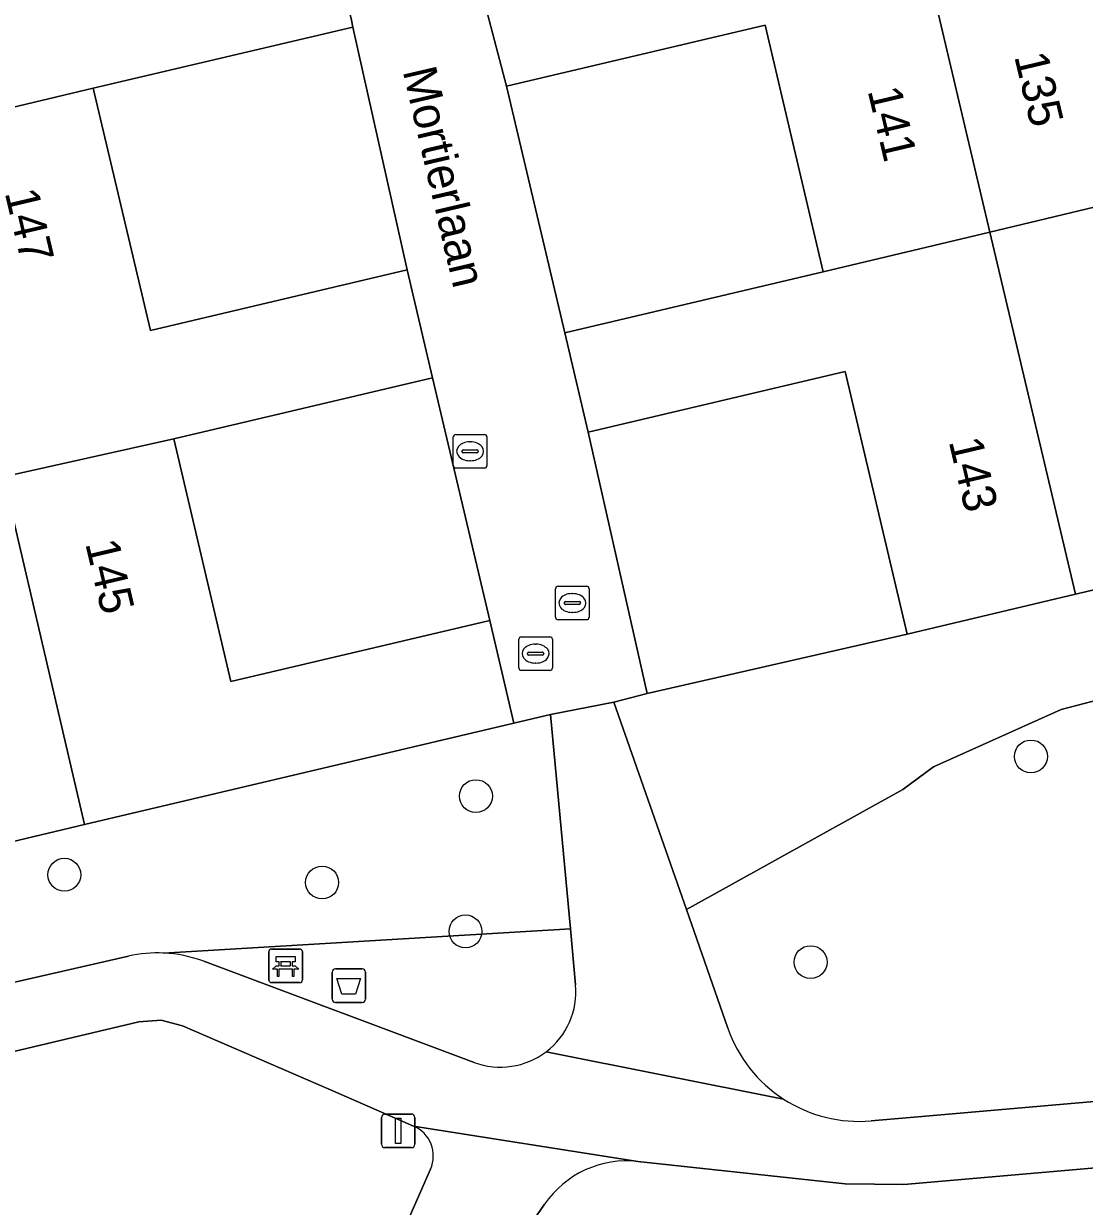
# Model space of a CAD drawing. Extents: x 162989 to 165008, y 383432 to 384338.
# Drawn here: x 164115.4 to 164146.97, y 383964.71 to 383999.9 of the extents above; entities that cross this region are included whole.
import ezdxf

# ---------------------------------------------------------------- set-up
doc = ezdxf.new("R2010")
doc.units = 0
for name, color, linetype in [('IMGEO_Afvalbak', 7, 'Continuous'), ('IMGEO_Bank', 7, 'Continuous'), ('IMGEO_Boom', 7, 'Continuous'), ('IMGEO_Brandkraan', 7, 'Continuous'), ('IMGEO_Erf', 7, 'Continuous'), ('IMGEO_Groenvoorziening', 7, 'Continuous'), ('IMGEO_Kolk', 7, 'Continuous'), ('IMGEO_Lichtmast', 7, 'Continuous'), ('IMGEO_Openbare_ruimte_label', 7, 'Continuous'), ('IMGEO_Pand', 7, 'Continuous'), ('IMGEO_Pand_nummerreeks', 7, 'Continuous'), ('IMGEO_Rioolput', 7, 'Continuous'), ('IMGEO_Voetpad_halfverhard', 7, 'Continuous'), ('IMGEO_Voetpad_open', 7, 'Continuous')]:
    doc.layers.add(name, color=color, linetype=linetype)

msp = doc.modelspace()

# ---------------------------------------------------------------- linework, layer by layer
at = {"layer": 'IMGEO_Afvalbak'}
for p, q in [((164124.581, 383970.875), (164124.581, 383971.675)), ((164124.581, 383971.675), (164124.581, 383970.875)), ((164124.681, 383971.775), (164125.471, 383971.775)), ((164125.471, 383971.775), (164124.681, 383971.775)), ((164125.571, 383971.675), (164125.571, 383970.875)), ((164125.571, 383970.875), (164125.571, 383971.675)), ((164125.471, 383970.775), (164124.681, 383970.775)), ((164124.681, 383970.775), (164125.471, 383970.775))]:
    msp.add_line(p, q, dxfattribs=at)
msp.add_lwpolyline([(164124.724, 383971.489), (164125.428, 383971.489), (164125.279, 383971.019), (164124.873, 383971.019), (164124.724, 383971.489)], dxfattribs=at)
for centre, start, end in [((164124.681, 383971.675), 90, 180), ((164124.681, 383971.675), 90, 180), ((164125.471, 383971.675), 0, 90), ((164125.471, 383971.675), 360, 90), ((164124.681, 383970.875), 180, 270), ((164124.681, 383970.875), 180, 270), ((164125.471, 383970.875), 270, 0), ((164125.471, 383970.875), 270, 0)]:
    msp.add_arc(centre, 0.1, start, end, dxfattribs=at)
at = {"layer": 'IMGEO_Bank'}
for p, q in [((164122.696, 383971.439), (164122.696, 383972.28)), ((164122.696, 383972.28), (164122.696, 383971.439)), ((164122.771, 383972.364), (164123.612, 383972.364)), ((164123.612, 383972.364), (164122.771, 383972.364)), ((164123.696, 383972.289), (164123.696, 383971.448)), ((164123.696, 383971.448), (164123.696, 383972.289)), ((164123.005, 383971.87), (164123.005, 383971.976)), ((164123.049, 383971.976), (164123.049, 383971.87)), ((164123.337, 383971.982), (164123.055, 383971.982)), ((164123.055, 383971.864), (164123.337, 383971.864)), ((164123.343, 383971.87), (164123.343, 383971.976)), ((164123.387, 383971.976), (164123.387, 383971.87)), ((164123.393, 383971.762), (164123, 383971.762)), ((164123.621, 383971.364), (164122.78, 383971.364)), ((164122.78, 383971.364), (164123.621, 383971.364))]:
    msp.add_line(p, q, dxfattribs=at)
for points in [[(164122.943, 383971.762), (164122.801, 383971.762), (164122.913, 383971.864), (164122.999, 383971.864)], [(164122.999, 383971.982), (164122.913, 383971.982), (164122.913, 383972.143), (164123.476, 383972.143), (164123.476, 383971.982), (164123.393, 383971.982)], [(164123.393, 383971.864), (164123.476, 383971.864), (164123.588, 383971.762), (164123.449, 383971.762)], [(164122.993, 383971.755), (164122.993, 383971.548), (164122.95, 383971.548), (164122.95, 383971.755)], [(164123.443, 383971.755), (164123.443, 383971.548), (164123.399, 383971.548), (164123.399, 383971.755)]]:
    msp.add_lwpolyline(points, dxfattribs=at)
for centre, radius, start, end in [((164122.774, 383972.286), 0.0779, 92.4484, 184.2845), ((164122.774, 383972.286), 0.0779, 92.4484, 184.2845), ((164123.618, 383972.286), 0.0779, 2.4484, 94.2845), ((164123.618, 383972.286), 0.0779, 2.4484, 94.2845), ((164122.998, 383971.975), 0.00671, 2.8957, 87.1043), ((164122.998, 383971.871), 0.00671, 272.8957, 357.1043), ((164123.055, 383971.975), 0.00671, 92.8957, 177.1043), ((164123.055, 383971.871), 0.00671, 182.8957, 267.1043), ((164123.337, 383971.975), 0.00671, 2.8957, 87.1043), ((164123.337, 383971.871), 0.00671, 272.8957, 357.1043), ((164123.394, 383971.975), 0.00671, 92.8957, 177.1043), ((164123.394, 383971.871), 0.00671, 182.8957, 267.1043), ((164122.943, 383971.755), 0.00671, 2.8957, 87.1043), ((164123, 383971.755), 0.00671, 92.8957, 177.1043), ((164123.392, 383971.755), 0.00671, 2.8957, 87.1043), ((164123.449, 383971.755), 0.00671, 92.8957, 177.1043), ((164123.618, 383971.442), 0.0779, 272.4484, 4.2845), ((164123.618, 383971.442), 0.0779, 272.4484, 4.2845), ((164122.774, 383971.442), 0.0779, 182.4484, 274.2845), ((164122.774, 383971.442), 0.0779, 182.4484, 274.2845)]:
    msp.add_arc(centre, radius, start, end, dxfattribs=at)
at = {"layer": 'IMGEO_Boom'}
for centre in [(164145.379, 383978.094), (164128.86, 383976.914), (164116.611, 383974.574), (164124.281, 383974.344), (164128.549, 383972.889), (164138.821, 383971.974)]:
    msp.add_circle(centre, 0.489, dxfattribs=at)
at = {"layer": 'IMGEO_Brandkraan'}
for p, q in [((164131.23, 383982.235), (164131.23, 383983.087)), ((164131.305, 383983.161), (164132.157, 383983.161)), ((164132.231, 383983.087), (164132.231, 383982.235)), ((164131.718, 383982.941), (164131.743, 383982.941)), ((164131.489, 383982.655), (164131.489, 383982.667)), ((164131.927, 383982.618), (164131.529, 383982.618)), ((164131.532, 383982.704), (164131.93, 383982.704)), ((164131.741, 383982.381), (164131.716, 383982.381)), ((164131.973, 383982.667), (164131.973, 383982.655)), ((164132.157, 383982.161), (164131.305, 383982.161))]:
    msp.add_line(p, q, dxfattribs=at)
for points in [[(164131.23, 383982.235), (164131.23, 383983.087)], [(164131.305, 383983.161), (164132.157, 383983.161)], [(164132.231, 383983.087), (164132.231, 383982.235)], [(164132.157, 383982.161), (164131.305, 383982.161)]]:
    msp.add_lwpolyline(points, dxfattribs=at)
for centre, radius, start, end in [((164131.307, 383983.085), 0.0765, 91.552, 178.448), ((164131.307, 383983.085), 0.0765, 91.552, 178.448), ((164132.155, 383983.085), 0.0765, 1.552, 88.448), ((164132.155, 383983.085), 0.0765, 1.552, 88.448), ((164131.529, 383982.664), 0.0403, 85.8775, 175.7526), ((164131.526, 383982.654), 0.0366, 178.938, 274.7102), ((164131.93, 383982.661), 0.043, 264.8664, 352.4533), ((164131.934, 383982.666), 0.0386, 1.7309, 96.639), ((164131.307, 383982.237), 0.0765, 181.552, 268.448), ((164131.307, 383982.237), 0.0765, 181.552, 268.448), ((164132.155, 383982.237), 0.0765, 271.552, 358.448), ((164132.155, 383982.237), 0.0765, 271.552, 358.448)]:
    msp.add_arc(centre, radius, start, end, dxfattribs=at)
for centre, major_axis, ratio, start_param, end_param in [((164131.717, 383982.661), (-0.387, 0.002), 0.722429, 4.712389, 7.853982), ((164131.742, 383982.661), (-0.39, 0.002), 0.717154, 1.570796, 4.712389)]:
    msp.add_ellipse(centre, major_axis=major_axis, ratio=ratio, start_param=start_param, end_param=end_param, dxfattribs=at)
at = {"layer": 'IMGEO_Erf'}
for points in [[(164125.199, 383999.801), (164117.47, 383997.977), (164119.171, 383990.768), (164126.813, 383992.571)], [(164131.502, 383990.704), (164139.198, 383992.52), (164137.466, 383999.857), (164129.77, 383998.041)], [(164141.692, 383981.736), (164139.849, 383989.547), (164132.201, 383987.742), (164133.953, 383979.965)], [(164127.57, 383989.362), (164119.865, 383987.544), (164121.568, 383980.327), (164129.269, 383982.144)]]:
    msp.add_lwpolyline(points, close=True, dxfattribs=at)
at = {"layer": 'IMGEO_Groenvoorziening'}
msp.add_lwpolyline([(164159.574, 383985.925), (164159.409, 383985.929), (164157.397, 383985.441), (164151.729, 383984.104), (164146.71, 383982.92), (164141.692, 383981.736), (164133.953, 383979.965), (164132.966, 383979.708), (164135.124, 383973.54), (164141.563, 383977.111), (164142.476, 383977.785), (164146.283, 383979.493), (164149.698, 383980.387), (164152.237, 383980.784), (164155.081, 383980.775), (164157.567, 383980.052), (164160.789, 383982.372), (164160.857, 383982.761), (164160.504, 383986.121)], close=True, dxfattribs=at)
for points in [[(164157.317, 383979.515), (164157.567, 383980.052), (164155.081, 383980.775), (164152.237, 383980.784), (164149.698, 383980.387), (164146.283, 383979.493), (164142.476, 383977.785), (164141.563, 383977.111), (164135.124, 383973.54), (164136.36, 383970.005)], [(164119.565, 383972.245), (164131.671, 383972.965), (164131.077, 383979.343), (164129.992, 383979.081), (164117.21, 383976.065), (164112.873, 383975.042), (164113.781, 383971.067), (164118.524, 383972.15)], [(164131.671, 383972.965), (164119.565, 383972.245)], [(164131.826, 383971.297), (164131.671, 383972.965)], [(164120.758, 383972.001), (164128.805, 383968.991)], [(164127.006, 383967.096), (164124.527, 383968.171), (164120.127, 383970.08), (164119.488, 383970.242), (164118.83, 383970.195), (164103.103, 383966.472), (164101.5, 383965.727), (164095.46, 383961.254), (164094.962, 383960.741), (164094.409, 383959.248), (164098.81, 383957.196), (164100.331, 383956.769), (164101.117, 383956.676), (164102.633, 383956.731), (164107.853, 383957.563), (164114.758, 383957.879), (164124.472, 383958.604), (164124.472, 383958.607), (164124.732, 383959.495), (164127.509, 383965.814)], [(164140.621, 383967.251), (164141.789, 383967.352), (164152.516, 383968.282)], [(164154.954, 383966.519), (164141.592, 383965.354), (164139.852, 383965.372), (164133.68, 383966.044)], [(164130.902, 383964.768), (164126.835, 383958.84), (164126.613, 383958.341), (164126.806, 383955.345), (164128.25, 383955.458), (164141.508, 383956.62), (164140.962, 383962.858), (164154.924, 383964.08), (164155.686, 383964.147), (164155.658, 383964.488), (164155.533, 383966.041)]]:
    msp.add_lwpolyline(points, dxfattribs=at)
for centre, radius, start, end in [((164119.391, 383968.402), 3.847, 87.4056, 103.0229), ((164119.392, 383968.359), 3.889, 69.4347, 87.4471), ((164129.593, 383971.092), 2.243, 307.3388, 5.2453), ((164140.261, 383971.37), 4.133, 199.284, 237.1481), ((164129.591, 383971.094), 2.245, 249.4968, 307.3455), ((164140.265, 383971.375), 4.139, 237.1369, 274.9357), ((164126.619, 383966.205), 0.972, 336.3011, 66.5445), ((164133.357, 383963.085), 2.977, 83.7737, 145.5671)]:
    msp.add_arc(centre, radius, start, end, dxfattribs=at)
at = {"layer": 'IMGEO_Kolk'}
for p, q in [((164128.261, 383987.675), (164129.113, 383987.675)), ((164128.186, 383986.749), (164128.186, 383987.601)), ((164128.674, 383987.455), (164128.699, 383987.455)), ((164129.187, 383987.601), (164129.187, 383986.749)), ((164128.445, 383987.169), (164128.445, 383987.181)), ((164128.883, 383987.132), (164128.485, 383987.132)), ((164128.488, 383987.218), (164128.886, 383987.218)), ((164128.929, 383987.181), (164128.929, 383987.169)), ((164129.113, 383986.675), (164128.261, 383986.675)), ((164128.697, 383986.895), (164128.672, 383986.895))]:
    msp.add_line(p, q, dxfattribs=at)
for points in [[(164128.261, 383987.675), (164129.113, 383987.675)], [(164128.186, 383986.749), (164128.186, 383987.601)], [(164129.187, 383987.601), (164129.187, 383986.749)], [(164129.113, 383986.675), (164128.261, 383986.675)]]:
    msp.add_lwpolyline(points, dxfattribs=at)
for centre, radius, start, end in [((164128.263, 383987.599), 0.0765, 91.552, 178.448), ((164128.263, 383987.599), 0.0765, 91.552, 178.448), ((164129.111, 383987.599), 0.0765, 1.552, 88.448), ((164129.111, 383987.599), 0.0765, 1.552, 88.448), ((164128.485, 383987.178), 0.0403, 85.8775, 175.7526), ((164128.482, 383987.168), 0.0366, 178.938, 274.7102), ((164128.886, 383987.175), 0.043, 264.8664, 352.4533), ((164128.89, 383987.18), 0.0386, 1.7309, 96.639), ((164128.263, 383986.751), 0.0765, 181.552, 268.448), ((164128.263, 383986.751), 0.0765, 181.552, 268.448), ((164129.111, 383986.751), 0.0765, 271.552, 358.448), ((164129.111, 383986.751), 0.0765, 271.552, 358.448)]:
    msp.add_arc(centre, radius, start, end, dxfattribs=at)
for centre, major_axis, ratio, start_param, end_param in [((164128.673, 383987.175), (-0.387, 0.002), 0.722429, 4.712389, 7.853982), ((164128.698, 383987.175), (-0.39, 0.002), 0.717154, 1.570796, 4.712389)]:
    msp.add_ellipse(centre, major_axis=major_axis, ratio=ratio, start_param=start_param, end_param=end_param, dxfattribs=at)
at = {"layer": 'IMGEO_Lichtmast'}
for p, q in [((164126.051, 383966.553), (164126.051, 383967.353)), ((164126.051, 383967.353), (164126.051, 383966.553)), ((164126.151, 383967.453), (164126.941, 383967.453)), ((164126.941, 383967.453), (164126.151, 383967.453)), ((164127.041, 383967.353), (164127.041, 383966.553)), ((164127.041, 383966.553), (164127.041, 383967.353)), ((164126.941, 383966.453), (164126.151, 383966.453)), ((164126.151, 383966.453), (164126.941, 383966.453))]:
    msp.add_line(p, q, dxfattribs=at)
msp.add_lwpolyline([(164126.471, 383967.328), (164126.621, 383967.328), (164126.621, 383966.578), (164126.471, 383966.578), (164126.471, 383967.328)], dxfattribs=at)
for centre, start, end in [((164126.151, 383967.353), 90, 180), ((164126.151, 383967.353), 90, 180), ((164126.941, 383967.353), 0, 90), ((164126.941, 383967.353), 360, 90), ((164126.151, 383966.553), 180, 270), ((164126.151, 383966.553), 180, 270), ((164126.941, 383966.553), 270, 0), ((164126.941, 383966.553), 270, 0)]:
    msp.add_arc(centre, 0.1, start, end, dxfattribs=at)
at = {"layer": 'IMGEO_Pand'}
for points in [[(164117.47, 383997.977), (164125.199, 383999.801), (164125.152, 384000), (164124.549, 384002.571), (164116.777, 384000.75), (164116.364, 384002.513), (164118.391, 384002.988), (164116.996, 384008.942), (164114.969, 384008.467), (164109.935, 384007.288), (164111.633, 384000), (164112.386, 383996.77)], [(164146.776, 384004.87), (164141.784, 384003.72), (164142.665, 384000), (164144.157, 383993.701), (164149.209, 383994.905), (164147.995, 384000), (164147.524, 384001.976), (164155.362, 384003.812), (164154.68, 384006.721)], [(164136.772, 384002.566), (164129.06, 384000.759), (164129.258, 384000), (164129.77, 383998.041), (164137.466, 383999.857), (164139.198, 383992.52), (164144.157, 383993.701), (164142.665, 384000), (164141.784, 384003.72)], [(164117.47, 383997.977), (164112.386, 383996.77), (164114.799, 383986.411), (164119.865, 383987.544), (164127.57, 383989.362), (164126.813, 383992.571), (164119.171, 383990.768)], [(164149.209, 383994.905), (164144.157, 383993.701), (164146.71, 383982.92), (164151.729, 383984.104), (164149.884, 383991.924), (164157.772, 383993.785), (164157.071, 383996.76), (164152.886, 383995.773)], [(164139.198, 383992.52), (164131.502, 383990.704), (164132.201, 383987.742), (164139.849, 383989.547), (164141.692, 383981.736), (164146.71, 383982.92), (164144.157, 383993.701)], [(164117.21, 383976.065), (164129.992, 383979.081), (164129.269, 383982.144), (164121.568, 383980.327), (164119.865, 383987.544), (164114.799, 383986.411)], [(164117.21, 383976.065), (164114.799, 383986.411), (164109.789, 383985.292), (164111.512, 383977.994), (164103.699, 383976.15), (164104.431, 383973.05), (164112.873, 383975.042)]]:
    msp.add_lwpolyline(points, close=True, dxfattribs=at)
at = {"layer": 'IMGEO_Rioolput'}
for p, q in [((164130.211, 383981.654), (164131.063, 383981.654)), ((164130.136, 383980.728), (164130.136, 383981.58)), ((164130.624, 383981.434), (164130.649, 383981.434)), ((164131.137, 383981.58), (164131.137, 383980.728)), ((164130.395, 383981.148), (164130.395, 383981.16)), ((164130.833, 383981.111), (164130.435, 383981.111)), ((164130.438, 383981.197), (164130.836, 383981.197)), ((164130.879, 383981.16), (164130.879, 383981.148)), ((164131.063, 383980.654), (164130.211, 383980.654)), ((164130.647, 383980.874), (164130.622, 383980.874))]:
    msp.add_line(p, q, dxfattribs=at)
for points in [[(164130.211, 383981.654), (164131.063, 383981.654)], [(164130.136, 383980.728), (164130.136, 383981.58)], [(164131.137, 383981.58), (164131.137, 383980.728)], [(164131.063, 383980.654), (164130.211, 383980.654)]]:
    msp.add_lwpolyline(points, dxfattribs=at)
for centre, radius, start, end in [((164130.213, 383981.578), 0.0765, 91.552, 178.448), ((164130.213, 383981.578), 0.0765, 91.552, 178.448), ((164131.061, 383981.578), 0.0765, 1.552, 88.448), ((164131.061, 383981.578), 0.0765, 1.552, 88.448), ((164130.435, 383981.157), 0.0403, 85.8775, 175.7526), ((164130.432, 383981.147), 0.0366, 178.938, 274.7102), ((164130.836, 383981.154), 0.043, 264.8664, 352.4533), ((164130.84, 383981.159), 0.0386, 1.7309, 96.639), ((164130.213, 383980.73), 0.0765, 181.552, 268.448), ((164130.213, 383980.73), 0.0765, 181.552, 268.448), ((164131.061, 383980.73), 0.0765, 271.552, 358.448), ((164131.061, 383980.73), 0.0765, 271.552, 358.448)]:
    msp.add_arc(centre, radius, start, end, dxfattribs=at)
for centre, major_axis, ratio, start_param, end_param in [((164130.623, 383981.154), (-0.387, 0.002), 0.722429, 4.712389, 7.853982), ((164130.648, 383981.154), (-0.39, 0.002), 0.717154, 1.570796, 4.712389)]:
    msp.add_ellipse(centre, major_axis=major_axis, ratio=ratio, start_param=start_param, end_param=end_param, dxfattribs=at)
at = {"layer": 'IMGEO_Voetpad_halfverhard'}
for points in [[(164132.966, 383979.708), (164131.077, 383979.343), (164131.671, 383972.965), (164131.826, 383971.297)], [(164136.36, 383970.005), (164135.124, 383973.54), (164132.966, 383979.708)], [(164118.524, 383972.15), (164113.781, 383971.067), (164107.618, 383969.659)], [(164128.805, 383968.991), (164120.758, 383972.001)], [(164091.324, 383954.477), (164091.478, 383952.667), (164093.763, 383952.722), (164093.505, 383955.612), (164093.579, 383956.38), (164094.409, 383959.248), (164094.962, 383960.741), (164095.46, 383961.254), (164101.5, 383965.727), (164103.103, 383966.472), (164118.83, 383970.195), (164119.488, 383970.242), (164120.127, 383970.08), (164124.527, 383968.171), (164127.006, 383967.096), (164133.68, 383966.044), (164139.852, 383965.372), (164141.592, 383965.354), (164154.954, 383966.519)], [(164130.953, 383969.309), (164138.019, 383967.898)], [(164138.019, 383967.898), (164130.953, 383969.309)], [(164152.516, 383968.282), (164141.789, 383967.352), (164140.621, 383967.251)], [(164133.68, 383966.044), (164127.006, 383967.096)], [(164127.509, 383965.814), (164124.732, 383959.495), (164124.472, 383958.607), (164124.472, 383958.604), (164124.716, 383955.108), (164126.806, 383955.345), (164126.613, 383958.341), (164126.835, 383958.84), (164130.902, 383964.768)]]:
    msp.add_lwpolyline(points, dxfattribs=at)
for centre, radius, start, end in [((164119.391, 383968.402), 3.847, 87.4056, 103.0229), ((164119.392, 383968.359), 3.889, 69.4347, 87.4471), ((164129.593, 383971.092), 2.243, 307.3388, 5.2453), ((164140.261, 383971.37), 4.133, 199.284, 237.1481), ((164129.591, 383971.094), 2.245, 249.4968, 307.3455), ((164140.265, 383971.375), 4.139, 237.1369, 274.9357), ((164126.619, 383966.205), 0.972, 336.3011, 66.5445), ((164133.357, 383963.085), 2.977, 83.7737, 145.5671)]:
    msp.add_arc(centre, radius, start, end, dxfattribs=at)
at = {"layer": 'IMGEO_Voetpad_open'}
msp.add_lwpolyline([(164129.77, 383998.041), (164129.258, 384000), (164129.06, 384000.759), (164127.219, 384008.037), (164126.482, 384011.183), (164122.726, 384010.313), (164124.549, 384002.571), (164125.152, 384000), (164125.199, 383999.801), (164126.813, 383992.571), (164127.57, 383989.362), (164129.269, 383982.144), (164129.992, 383979.081), (164131.077, 383979.343), (164132.966, 383979.708), (164133.953, 383979.965), (164132.201, 383987.742), (164131.502, 383990.704)], close=True, dxfattribs=at)

# ---------------------------------------------------------------- texts
at = {"layer": 'IMGEO_Openbare_ruimte_label'}
msp.add_text('Mortierlaan', height=1, rotation=283.1749, dxfattribs=at).set_placement((164126.677, 383998.494))
at = {"layer": 'IMGEO_Pand_nummerreeks'}
for s, rotation, p in [('135', 283.4035, (164144.877, 383998.932)), ('141', 283.2823, (164140.514, 383997.91)), ('147', 283.2764, (164114.832, 383994.873)), ('143', 283.2761, (164142.927, 383987.473)), ('145', 283.2772, (164117.228, 383984.435))]:
    msp.add_text(s, height=1, rotation=rotation, dxfattribs=at).set_placement(p)

doc.saveas('drawing.dxf')
